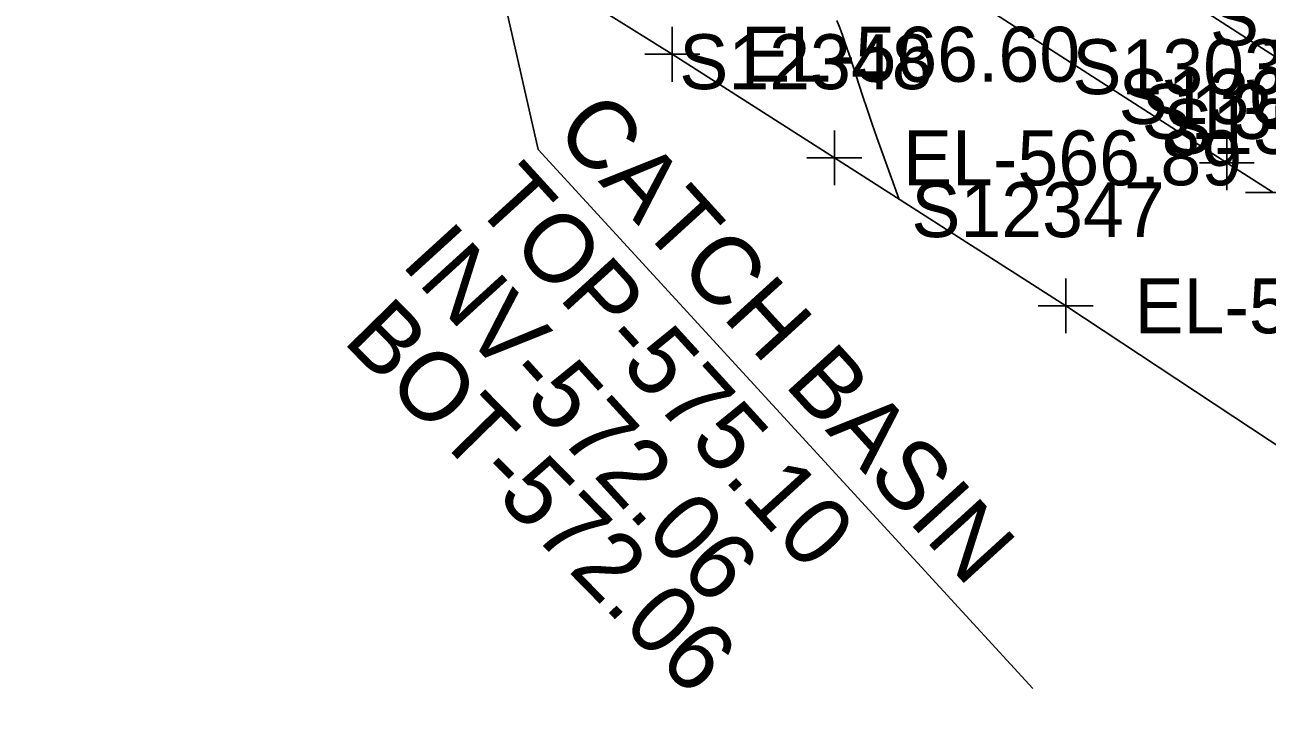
# Model space of a CAD drawing. Extents: x 1729869 to 1735532, y 648588 to 653771.
# Drawn here: x 1730731.9 to 1730822.3, y 652323.9 to 652374.7 of the extents above; entities that cross this region are included whole.
import ezdxf

# ---------------------------------------------------------------- set-up
doc = ezdxf.new("R2010")
doc.units = 0
for name, color, linetype in [('SURVEY - CONTOURS - Intermediate with optional Text', 7, 'Continuous'), ('SURVEY - DRAINAGE - Storm Sewer Text', 7, 'Continuous'), ('SURVEY - MISCELLANEOUS - Bottom of MH and CB', 7, 'Continuous'), ('SURVEY - TRANSPORTATION - Features', 7, 'Continuous'), ('SURVEY - TRANSPORTATION - Features - Points - Numbers', 7, 'Continuous'), ('SURVEY - TRANSPORTATION - Roads', 7, 'Continuous'), ('SURVEY - TRANSPORTATION - Roads - Points - Elevations', 7, 'Continuous'), ('SURVEY - TRANSPORTATION - Roads - Points - Locators', 7, 'Continuous'), ('SURVEY - TRANSPORTATION - Roads - Points - Numbers', 7, 'Continuous')]:
    doc.layers.add(name, color=color, linetype=linetype)

msp = doc.modelspace()

# ---------------------------------------------------------------- linework, layer by layer
at = {"layer": 'SURVEY - CONTOURS - Intermediate with optional Text'}
msp.add_lwpolyline([(1730795.569, 652362.006), (1730794.994, 652363.56), (1730794.584, 652364.685), (1730794.146, 652365.901), (1730793.926, 652366.521), (1730793.589, 652367.484), (1730793.241, 652368.508), (1730792.889, 652369.567), (1730792.157, 652371.817), (1730791.979, 652372.354), (1730791.796, 652372.898), (1730791.607, 652373.447), (1730791.421, 652373.975), (1730791.229, 652374.507), (1730791.031, 652375.042)], dxfattribs=at)
at = {"layer": 'SURVEY - DRAINAGE - Storm Sewer Text'}
for p in [(1730745.544, 652471.171), (1730805.294, 652326.381)]:
    msp.add_line(p, (1730769.273, 652365.628), dxfattribs=at)
at = {"layer": 'SURVEY - TRANSPORTATION - Features'}
msp.add_lwpolyline([(1730679.148, 652458.959), (1730700.909, 652446.658), (1730722.72, 652434.139), (1730744.445, 652421.455), (1730765.867, 652408.433), (1730787.104, 652395.248), (1730808.362, 652381.812), (1730829.417, 652368.203), (1730850.292, 652354.449), (1730871.15, 652340.343), (1730891.852, 652326.16), (1730912.257, 652311.717), (1730932.625, 652297.091), (1730952.92, 652282.174), (1730972.943, 652267.104), (1730977.983, 652263.095), (1730980.577, 652261.164), (1730985.786, 652257.149), (1731000.693, 652245.44)], dxfattribs=at)
at = {"layer": 'SURVEY - TRANSPORTATION - Roads'}
for points in [[(1730649.217, 652465.696), (1730673.763, 652452.23), (1730705.199, 652434.694), (1730734.582, 652417.595), (1730758.505, 652403.052), (1730784.006, 652387.256), (1730797.557, 652378.752), (1730819.407, 652364.667), (1730822.769, 652362.499)], [(1730842.714, 652331.091), (1730807.686, 652354.257), (1730790.839, 652365.031), (1730779.046, 652372.572), (1730768.87, 652378.929), (1730733.06, 652400.865), (1730706.465, 652416.408), (1730677.106, 652433.11), (1730650.892, 652447.449), (1730639.01, 652453.881), (1730623.049, 652462.2)]]:
    msp.add_lwpolyline(points, dxfattribs=at)
at = {"layer": 'SURVEY - TRANSPORTATION - Roads - Points - Locators'}
for p, q in [((1730779.046, 652374.572), (1730779.046, 652370.572)), ((1730781.046, 652372.572), (1730777.046, 652372.572)), ((1730790.839, 652367.031), (1730790.839, 652363.031)), ((1730819.407, 652366.667), (1730819.407, 652362.667)), ((1730792.839, 652365.031), (1730788.839, 652365.031)), ((1730821.407, 652364.667), (1730817.407, 652364.667)), ((1730824.769, 652362.499), (1730820.769, 652362.499)), ((1730807.686, 652356.257), (1730807.686, 652352.257)), ((1730809.686, 652354.257), (1730805.686, 652354.257))]:
    msp.add_line(p, q, dxfattribs=at)

# ---------------------------------------------------------------- texts
at = {"layer": 'SURVEY - DRAINAGE - Storm Sewer Text'}
for s, p in [('CATCH BASIN', (1730770.352, 652366.895)), ('TOP-575.10', (1730764.438, 652361.692)), ('INV-572.06', (1730759.202, 652357.295))]:
    msp.add_text(s, height=5, rotation=312.34085, dxfattribs=at).set_placement(p)
at = {"layer": 'SURVEY - MISCELLANEOUS - Bottom of MH and CB'}
msp.add_text('BOT-572.06', height=5, rotation=314.50899, dxfattribs=at).set_placement((1730754.98, 652351.663))
at = {"layer": 'SURVEY - TRANSPORTATION - Features - Points - Numbers'}
msp.add_text('S13733', height=4, dxfattribs=at).set_placement((1730818.177, 652373.203))
at = {"layer": 'SURVEY - TRANSPORTATION - Roads - Points - Elevations'}
for s, p in [('EL-566.60', (1730784.046, 652370.572)), ('EL-566.89', (1730795.839, 652363.031)), ('EL-567.27', (1730812.686, 652352.257))]:
    msp.add_text(s, height=4, dxfattribs=at).set_placement(p)
at = {"layer": 'SURVEY - TRANSPORTATION - Roads - Points - Numbers'}
for s, p in [('S12348', (1730779.552, 652370.031)), ('S13033', (1730808.167, 652369.667)), ('S13034', (1730811.529, 652367.499)), ('S13035', (1730813.209, 652366.415)), ('S13036', (1730814.771, 652365.318)), ('S12347', (1730796.446, 652359.257))]:
    msp.add_text(s, height=4, dxfattribs=at).set_placement(p)

doc.saveas('drawing.dxf')
